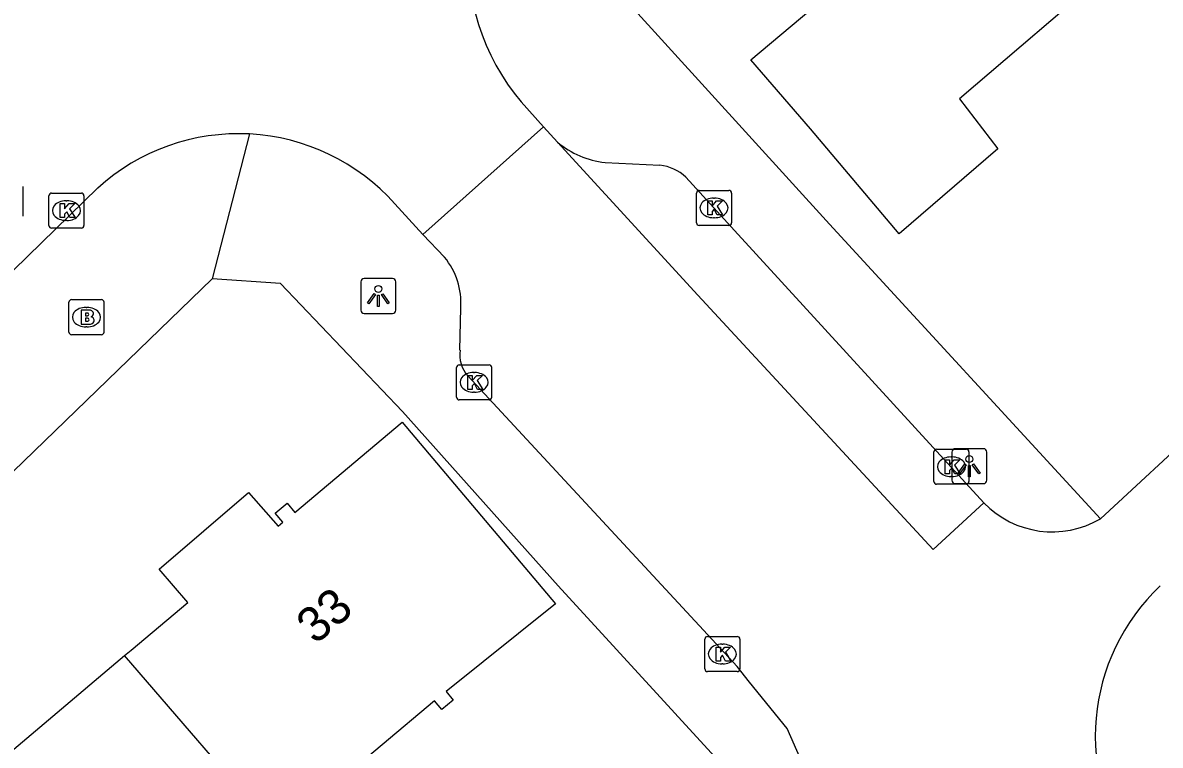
# Model space of a CAD drawing. Extents: x 157466 to 158888, y 383063 to 384677.
# Drawn here: x 157958.89 to 157991.34, y 383616.61 to 383637.24 of the extents above; entities that cross this region are included whole.
import ezdxf

# ---------------------------------------------------------------- set-up
doc = ezdxf.new("R2010")
doc.units = 0
for name, color, linetype in [('IMGEO_Brandkraan', 7, 'Continuous'), ('IMGEO_Kolk', 7, 'Continuous'), ('IMGEO_Lichtpunt', 7, 'Continuous'), ('IMGEO_Muur', 7, 'Continuous'), ('IMGEO_Pand', 7, 'Continuous'), ('IMGEO_Pand_nummerreeks', 7, 'Continuous'), ('IMGEO_Rijbaan_lokaal_open', 7, 'Continuous'), ('IMGEO_Rioolput', 7, 'Continuous'), ('IMGEO_Voetpad_open', 7, 'Continuous')]:
    doc.layers.add(name, color=color, linetype=linetype)

msp = doc.modelspace()

# ---------------------------------------------------------------- linework, layer by layer
at = {"layer": 'IMGEO_Brandkraan'}
for p, q in [((157960.21, 383628.407), (157960.21, 383629.259)), ((157960.285, 383629.333), (157961.137, 383629.333)), ((157961.211, 383629.259), (157961.211, 383628.407)), ((157960.698, 383629.113), (157960.723, 383629.113)), ((157960.721, 383628.553), (157960.696, 383628.553)), ((157961.137, 383628.333), (157960.285, 383628.333))]:
    msp.add_line(p, q, dxfattribs=at)
for points in [[(157960.21, 383628.407), (157960.21, 383629.259)], [(157960.285, 383629.333), (157961.137, 383629.333)], [(157961.211, 383629.259), (157961.211, 383628.407)], [(157960.558, 383629.033), (157960.558, 383628.633), (157960.771, 383628.633)], [(157960.789, 383629.033), (157960.558, 383629.033)], [(157960.737, 383628.952), (157960.683, 383628.952), (157960.683, 383628.876)], [(157960.683, 383628.876), (157960.736, 383628.876)], [(157960.745, 383628.8), (157960.683, 383628.8), (157960.683, 383628.719)], [(157960.683, 383628.719), (157960.745, 383628.719)], [(157961.137, 383628.333), (157960.285, 383628.333)]]:
    msp.add_lwpolyline(points, dxfattribs=at)
for centre, radius, start, end in [((157960.287, 383629.257), 0.0765, 91.552, 178.448), ((157960.287, 383629.257), 0.0765, 91.552, 178.448), ((157961.135, 383629.257), 0.0765, 1.552, 88.448), ((157961.135, 383629.257), 0.0765, 1.552, 88.448), ((157960.738, 383628.914), 0.0379, 267.8285, 90.9355), ((157960.793, 383628.888), 0.145, 59.4692, 91.5367), ((157960.818, 383628.935), 0.0922, 285.5137, 58.1501), ((157960.823, 383628.743), 0.105, 301.3115, 78.989), ((157960.746, 383628.759), 0.0404, 269.8759, 90.5077), ((157960.777, 383628.884), 0.251, 268.6676, 293.5347), ((157960.287, 383628.409), 0.0765, 181.552, 268.448), ((157960.287, 383628.409), 0.0765, 181.552, 268.448), ((157961.135, 383628.409), 0.0765, 271.552, 358.448), ((157961.135, 383628.409), 0.0765, 271.552, 358.448)]:
    msp.add_arc(centre, radius, start, end, dxfattribs=at)
for centre, major_axis, ratio, start_param, end_param in [((157960.697, 383628.833), (-0.387, 0.002), 0.722429, 4.712389, 7.853982), ((157960.722, 383628.833), (-0.39, 0.002), 0.717154, 1.570796, 4.712389)]:
    msp.add_ellipse(centre, major_axis=major_axis, ratio=ratio, start_param=start_param, end_param=end_param, dxfattribs=at)
at = {"layer": 'IMGEO_Kolk'}
for p, q in [((157978.187, 383632.452), (157979.039, 383632.452)), ((157959.639, 383631.449), (157959.639, 383632.301)), ((157959.714, 383632.375), (157960.566, 383632.375)), ((157960.127, 383632.155), (157960.152, 383632.155)), ((157960.64, 383632.301), (157960.64, 383631.449)), ((157978.112, 383631.526), (157978.112, 383632.378)), ((157978.6, 383632.232), (157978.625, 383632.232)), ((157979.113, 383632.378), (157979.113, 383631.526)), ((157960.15, 383631.595), (157960.125, 383631.595)), ((157979.039, 383631.452), (157978.187, 383631.452)), ((157978.623, 383631.672), (157978.598, 383631.672)), ((157960.566, 383631.375), (157959.714, 383631.375)), ((157971.268, 383626.546), (157971.268, 383627.398)), ((157971.343, 383627.472), (157972.195, 383627.472)), ((157971.756, 383627.252), (157971.781, 383627.252)), ((157972.269, 383627.398), (157972.269, 383626.546)), ((157971.779, 383626.692), (157971.754, 383626.692)), ((157972.195, 383626.472), (157971.343, 383626.472)), ((157984.884, 383624.137), (157984.884, 383624.989)), ((157984.959, 383625.063), (157985.811, 383625.063)), ((157985.885, 383624.989), (157985.885, 383624.137)), ((157985.372, 383624.843), (157985.397, 383624.843)), ((157985.395, 383624.283), (157985.37, 383624.283)), ((157985.811, 383624.063), (157984.959, 383624.063)), ((157978.349, 383618.79), (157978.349, 383619.642)), ((157978.424, 383619.716), (157979.276, 383619.716)), ((157978.837, 383619.496), (157978.862, 383619.496)), ((157979.35, 383619.642), (157979.35, 383618.79)), ((157978.86, 383618.936), (157978.835, 383618.936)), ((157979.276, 383618.716), (157978.424, 383618.716))]:
    msp.add_line(p, q, dxfattribs=at)
for points in [[(157978.187, 383632.452), (157979.039, 383632.452)], [(157959.639, 383631.449), (157959.639, 383632.301)], [(157959.714, 383632.375), (157960.566, 383632.375)], [(157959.96, 383632.075), (157960.083, 383632.075), (157960.083, 383631.924), (157960.213, 383632.075), (157960.377, 383632.075), (157960.231, 383631.924), (157960.384, 383631.675), (157960.232, 383631.675), (157960.147, 383631.839), (157960.083, 383631.772), (157960.083, 383631.675), (157959.96, 383631.675), (157959.96, 383632.075)], [(157960.64, 383632.301), (157960.64, 383631.449)], [(157978.112, 383631.526), (157978.112, 383632.378)], [(157978.433, 383632.152), (157978.556, 383632.152), (157978.556, 383632.001), (157978.686, 383632.152), (157978.85, 383632.152), (157978.704, 383632.001), (157978.857, 383631.752), (157978.705, 383631.752), (157978.62, 383631.916), (157978.556, 383631.849), (157978.556, 383631.752), (157978.433, 383631.752), (157978.433, 383632.152)], [(157979.113, 383632.378), (157979.113, 383631.526)], [(157979.039, 383631.452), (157978.187, 383631.452)], [(157960.566, 383631.375), (157959.714, 383631.375)], [(157971.268, 383626.546), (157971.268, 383627.398)], [(157971.343, 383627.472), (157972.195, 383627.472)], [(157972.269, 383627.398), (157972.269, 383626.546)], [(157971.589, 383627.172), (157971.712, 383627.172), (157971.712, 383627.021), (157971.842, 383627.172), (157972.006, 383627.172), (157971.86, 383627.021), (157972.013, 383626.772), (157971.861, 383626.772), (157971.776, 383626.936), (157971.712, 383626.869), (157971.712, 383626.772), (157971.589, 383626.772), (157971.589, 383627.172)], [(157972.195, 383626.472), (157971.343, 383626.472)], [(157984.884, 383624.137), (157984.884, 383624.989)], [(157984.959, 383625.063), (157985.811, 383625.063)], [(157985.885, 383624.989), (157985.885, 383624.137)], [(157985.205, 383624.763), (157985.328, 383624.763), (157985.328, 383624.612), (157985.458, 383624.763), (157985.622, 383624.763), (157985.476, 383624.612), (157985.629, 383624.363), (157985.477, 383624.363), (157985.392, 383624.527), (157985.328, 383624.46), (157985.328, 383624.363), (157985.205, 383624.363), (157985.205, 383624.763)], [(157985.811, 383624.063), (157984.959, 383624.063)], [(157978.349, 383618.79), (157978.349, 383619.642)], [(157978.424, 383619.716), (157979.276, 383619.716)], [(157978.67, 383619.416), (157978.793, 383619.416), (157978.793, 383619.265), (157978.923, 383619.416), (157979.087, 383619.416), (157978.941, 383619.265), (157979.094, 383619.016), (157978.942, 383619.016), (157978.857, 383619.18), (157978.793, 383619.113), (157978.793, 383619.016), (157978.67, 383619.016), (157978.67, 383619.416)], [(157979.35, 383619.642), (157979.35, 383618.79)], [(157979.276, 383618.716), (157978.424, 383618.716)]]:
    msp.add_lwpolyline(points, dxfattribs=at)
for centre, start, end in [((157978.189, 383632.376), 91.552, 178.448), ((157978.189, 383632.376), 91.552, 178.448), ((157979.037, 383632.376), 1.552, 88.448), ((157979.037, 383632.376), 1.552, 88.448), ((157959.716, 383632.299), 91.552, 178.448), ((157959.716, 383632.299), 91.552, 178.448), ((157960.564, 383632.299), 1.552, 88.448), ((157960.564, 383632.299), 1.552, 88.448), ((157959.716, 383631.451), 181.552, 268.448), ((157959.716, 383631.451), 181.552, 268.448), ((157960.564, 383631.451), 271.552, 358.448), ((157960.564, 383631.451), 271.552, 358.448), ((157978.189, 383631.528), 181.552, 268.448), ((157978.189, 383631.528), 181.552, 268.448), ((157979.037, 383631.528), 271.552, 358.448), ((157979.037, 383631.528), 271.552, 358.448), ((157971.345, 383627.396), 91.552, 178.448), ((157971.345, 383627.396), 91.552, 178.448), ((157972.193, 383627.396), 1.552, 88.448), ((157972.193, 383627.396), 1.552, 88.448), ((157971.345, 383626.548), 181.552, 268.448), ((157971.345, 383626.548), 181.552, 268.448), ((157972.193, 383626.548), 271.552, 358.448), ((157972.193, 383626.548), 271.552, 358.448), ((157984.961, 383624.987), 91.552, 178.448), ((157984.961, 383624.987), 91.552, 178.448), ((157985.809, 383624.987), 1.552, 88.448), ((157985.809, 383624.987), 1.552, 88.448), ((157984.961, 383624.139), 181.552, 268.448), ((157984.961, 383624.139), 181.552, 268.448), ((157985.809, 383624.139), 271.552, 358.448), ((157985.809, 383624.139), 271.552, 358.448), ((157978.426, 383619.64), 91.552, 178.448), ((157978.426, 383619.64), 91.552, 178.448), ((157979.274, 383619.64), 1.552, 88.448), ((157979.274, 383619.64), 1.552, 88.448), ((157978.426, 383618.792), 181.552, 268.448), ((157978.426, 383618.792), 181.552, 268.448), ((157979.274, 383618.792), 271.552, 358.448), ((157979.274, 383618.792), 271.552, 358.448)]:
    msp.add_arc(centre, 0.0765, start, end, dxfattribs=at)
for centre, major_axis, ratio, start_param, end_param in [((157960.126, 383631.875), (-0.387, 0.002), 0.722429, 4.712389, 7.853982), ((157960.151, 383631.875), (-0.39, 0.002), 0.717154, 1.570796, 4.712389), ((157978.599, 383631.952), (-0.387, 0.002), 0.722429, 4.712389, 7.853982), ((157978.624, 383631.952), (-0.39, 0.002), 0.717154, 1.570796, 4.712389), ((157971.755, 383626.972), (-0.387, 0.002), 0.722429, 4.712389, 7.853982), ((157971.78, 383626.972), (-0.39, 0.002), 0.717154, 1.570796, 4.712389), ((157985.371, 383624.563), (-0.387, 0.002), 0.722429, 4.712389, 7.853982), ((157985.396, 383624.563), (-0.39, 0.002), 0.717154, 1.570796, 4.712389), ((157978.836, 383619.216), (-0.387, 0.002), 0.722429, 4.712389, 7.853982), ((157978.861, 383619.216), (-0.39, 0.002), 0.717154, 1.570796, 4.712389)]:
    msp.add_ellipse(centre, major_axis=major_axis, ratio=ratio, start_param=start_param, end_param=end_param, dxfattribs=at)
at = {"layer": 'IMGEO_Lichtpunt'}
for p, q in [((157968.539, 383629.841), (157968.539, 383629.034)), ((157968.539, 383629.841), (157968.539, 383629.034)), ((157969.441, 383629.936), (157968.633, 383629.936)), ((157969.441, 383629.936), (157968.633, 383629.936)), ((157969.535, 383629.034), (157969.535, 383629.841)), ((157969.535, 383629.034), (157969.535, 383629.841)), ((157968.633, 383628.94), (157969.441, 383628.94)), ((157968.633, 383628.94), (157969.441, 383628.94)), ((157985.394, 383624.983), (157985.394, 383624.176)), ((157985.394, 383624.983), (157985.394, 383624.176)), ((157986.296, 383625.078), (157985.488, 383625.078)), ((157986.296, 383625.078), (157985.488, 383625.078)), ((157986.39, 383624.176), (157986.39, 383624.983)), ((157986.39, 383624.176), (157986.39, 383624.983)), ((157985.488, 383624.082), (157986.296, 383624.082)), ((157985.488, 383624.082), (157986.296, 383624.082))]:
    msp.add_line(p, q, dxfattribs=at)
for points in [[(157968.913, 383629.505), (157968.952, 383629.477), (157968.764, 383629.215), (157968.726, 383629.242), (157968.913, 383629.505)], [(157969.125, 383629.477), (157969.163, 383629.504), (157969.35, 383629.242), (157969.311, 383629.214), (157969.125, 383629.477)], [(157969.015, 383629.457), (157969.062, 383629.457), (157969.062, 383629.135), (157969.015, 383629.135), (157969.015, 383629.457)], [(157985.768, 383624.647), (157985.807, 383624.619), (157985.619, 383624.357), (157985.581, 383624.384), (157985.768, 383624.647)], [(157985.98, 383624.619), (157986.018, 383624.646), (157986.205, 383624.384), (157986.166, 383624.356), (157985.98, 383624.619)], [(157985.87, 383624.599), (157985.917, 383624.599), (157985.917, 383624.277), (157985.87, 383624.277), (157985.87, 383624.599)]]:
    msp.add_lwpolyline(points, dxfattribs=at)
for centre in [(157969.038, 383629.639), (157985.893, 383624.781)]:
    msp.add_circle(centre, 0.0994, dxfattribs=at)
for centre, start, end in [((157968.633, 383629.841), 90, 180), ((157968.633, 383629.841), 90, 180), ((157969.441, 383629.841), 0, 90), ((157969.441, 383629.841), 0, 90), ((157968.633, 383629.034), 180, 270), ((157968.633, 383629.034), 180, 270), ((157969.441, 383629.034), 270, 0), ((157969.441, 383629.034), 270, 360), ((157985.488, 383624.983), 90, 180), ((157985.488, 383624.983), 90, 180), ((157986.296, 383624.983), 0, 90), ((157986.296, 383624.983), 0, 90), ((157985.488, 383624.176), 180, 270), ((157985.488, 383624.176), 180, 270), ((157986.296, 383624.176), 270, 0), ((157986.296, 383624.176), 270, 360)]:
    msp.add_arc(centre, 0.0946, start, end, dxfattribs=at)
at = {"layer": 'IMGEO_Muur'}
for points in [[(157989.635, 383623.079), (157981.903, 383631.484)], [(157992.577, 383625.793), (157989.635, 383623.079)], [(157980.818, 383613.893), (157974.166, 383621.166)]]:
    msp.add_lwpolyline(points, dxfattribs=at)
at = {"layer": 'IMGEO_Pand'}
for points in [[(157989.977, 383638.805), (157985.615, 383635.071), (157986.707, 383633.642), (157983.891, 383631.215), (157981.361, 383634.206), (157979.663, 383636.182), (157982.254, 383638.373), (157980.803, 383640.07), (157981.089, 383640.365), (157981.292, 383640.129), (157985.631, 383643.855)], [(157961.8, 383619.174), (157961.984, 383619.329), (157963.598, 383620.69), (157962.781, 383621.643), (157965.33, 383623.828), (157966.177, 383622.867), (157966.314, 383622.982), (157966.097, 383623.24), (157966.432, 383623.523), (157966.658, 383623.256), (157969.716, 383625.835), (157974.088, 383620.653), (157970.967, 383618.146), (157971.174, 383617.901), (157970.851, 383617.629), (157970.638, 383617.881), (157966.164, 383614.107)], [(157957.325, 383615.4), (157961.8, 383619.174)], [(157966.164, 383614.107), (157961.8, 383619.174)]]:
    msp.add_lwpolyline(points, dxfattribs=at)
at = {"layer": 'IMGEO_Rijbaan_lokaal_open'}
for points in [[(157973.109, 383634.978), (157973.75, 383634.264)], [(157970.307, 383631.191), (157973.75, 383634.264)], [(157973.75, 383634.264), (157974.148, 383633.825)], [(157986.309, 383623.532), (157984.864, 383622.204), (157978.152, 383629.463), (157974.148, 383633.825)], [(157957.41, 383628.994), (157961.035, 383632.521)], [(157970.307, 383631.191), (157969.509, 383632.071)], [(157970.926, 383630.545), (157970.307, 383631.191)], [(157971.366, 383627.892), (157971.389, 383629.102)], [(157980.818, 383613.893), (157981.11, 383614.2), (157981.29, 383614.468), (157981.365, 383614.806), (157981.367, 383615.093), (157981.263, 383615.7), (157981.081, 383616.228), (157980.7, 383617.094), (157979.626, 383618.411), (157979.269, 383618.86), (157971.586, 383627.161)], [(157989.635, 383623.079), (157992.577, 383625.793)]]:
    msp.add_lwpolyline(points, dxfattribs=at)
for centre, radius, start, end in [((157978.186, 383639.204), 6.605, 175.7246, 219.77), ((157965.051, 383628.095), 5.976, 86.9775, 132.2178), ((157965.051, 383628.104), 5.967, 41.6649, 86.9776), ((157969.318, 383629.233), 2.075, 356.3763, 39.2023), ((157972.26, 383627.762), 0.903, 171.7483, 221.7509), ((157988.259, 383625.411), 2.708, 223.9407, 300.5474), ((157995.406, 383616.857), 5.92, 133.3577, 216.3777)]:
    msp.add_arc(centre, radius, start, end, dxfattribs=at)
at = {"layer": 'IMGEO_Rioolput'}
msp.add_line((157958.893, 383632.567), (157958.893, 383631.715), dxfattribs=at)
msp.add_lwpolyline([(157958.893, 383632.567), (157958.893, 383631.715)], dxfattribs=at)
at = {"layer": 'IMGEO_Voetpad_open'}
for points in [[(157989.635, 383623.079), (157981.903, 383631.484), (157976.157, 383637.817), (157976.459, 383641.091)], [(157965.366, 383634.063), (157964.293, 383629.929)], [(157975.504, 383633.249), (157977.068, 383633.17)], [(157977.81, 383632.83), (157979.201, 383631.311), (157986.309, 383623.532)], [(157964.293, 383629.929), (157929.336, 383596.06)], [(157980.818, 383613.893), (157974.166, 383621.166), (157969.729, 383626.144), (157966.242, 383629.799), (157964.293, 383629.929)]]:
    msp.add_lwpolyline(points, dxfattribs=at)
for centre, radius, start, end in [((157975.791, 383635.81), 2.577, 230.3734, 263.5971), ((157976.918, 383631.863), 1.316, 47.3136, 83.4499)]:
    msp.add_arc(centre, radius, start, end, dxfattribs=at)

# ---------------------------------------------------------------- texts
at = {"layer": 'IMGEO_Pand_nummerreeks'}
msp.add_text('33', height=1, rotation=40.0793, dxfattribs=at).set_placement((157967.24, 383619.465))

doc.saveas('drawing.dxf')
